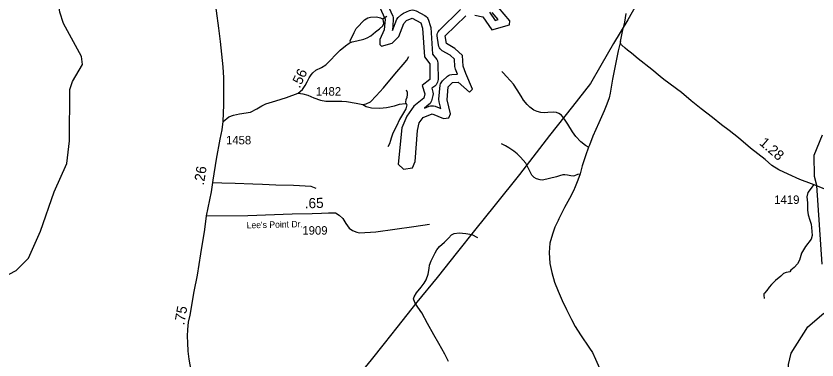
# Model space of a CAD drawing. Extents: x 2290615 to 2522933, y 819489 to 1012715.
# Drawn here: x 2339390 to 2351212, y 992330 to 997402 of the extents above; entities that cross this region are included whole.
import ezdxf

# ---------------------------------------------------------------- set-up
doc = ezdxf.new("R2010")
doc.units = 0
for name, color, linetype in [('Exist Hydrographic Buffer Line', 7, 'Continuous'), ('Exist Hydrographic Creek Single Shore', 7, 'Continuous'), ('Exist Hydrographic Lake Shore', 7, 'Continuous'), ('Exist Hydrographic Misc Water Feature', 7, 'Continuous'), ('Exist Road Non-System Type 51', 7, 'Continuous'), ('Exist Road Secondary Mileage Tenths English Label', 7, 'Continuous'), ('Exist Road Secondary Type 51 Attributed', 7, 'Continuous'), ('Exist Road Secondary Type 51 Label', 7, 'Continuous'), ('Exist Road Secondary Type 51 Number Label', 7, 'Continuous'), ('Exist Utilities Electrical Transmission Line', 7, 'Continuous')]:
    doc.layers.add(name, color=color, linetype=linetype)

msp = doc.modelspace()

# ---------------------------------------------------------------- linework, layer by layer
at = {"layer": 'Exist Hydrographic Buffer Line'}
for points in [[(2344862, 997590), (2344951, 997399), (2344956, 997379), (2344958, 997347), (2344945, 997188)], [(2344945, 997188), (2345010, 997354), (2345029, 997379), (2345078, 997427), (2345107, 997445), (2345197, 997484), (2345217, 997490), (2345238, 997491), (2345259, 997490), (2345294, 997477), (2345424, 997408), (2345441, 997396), (2345456, 997382), (2345468, 997364), (2345478, 997341), (2345504, 997260), (2345510, 997232), (2345537, 996842), (2345600, 996759)], [(2345662, 996036), (2345636, 996139), (2345632, 996178), (2345649, 996380), (2345654, 996400), (2345663, 996419), (2345685, 996447), (2345756, 996513), (2345773, 996525), (2345792, 996534), (2345823, 996541), (2345905, 996547), (2345876, 996620), (2345868, 996656), (2345861, 996765), (2345797, 996824), (2345682, 996891), (2345665, 996903), (2345650, 996918), (2345638, 996935), (2345629, 996954), (2345624, 996976), (2345604, 997109), (2345606, 997130), (2345611, 997150), (2345620, 997169), (2345641, 997195), (2345952, 997496)], [(2346377, 997461), (2346464, 997338), (2346506, 997349), (2346419, 997452)], [(2345600, 996759), (2345609, 996740), (2345616, 996701), (2345619, 996466), (2345617, 996446), (2345612, 996425), (2345603, 996406), (2345591, 996389), (2345571, 996370), (2345525, 996336), (2345544, 996277), (2345546, 996257), (2345543, 996228), (2345523, 996149), (2345514, 996130), (2345502, 996113), (2345485, 996096), (2345420, 996045), (2345489, 996072), (2345509, 996077), (2345530, 996079), (2345551, 996077), (2345574, 996071), (2345662, 996036)]]:
    msp.add_lwpolyline(points, dxfattribs=at)
at = {"layer": 'Exist Hydrographic Creek Single Shore'}
for points in [[(2351289, 993744), (2351208, 994903), (2351173, 995036), (2351169, 995351), (2351291, 995651)], [(2348630, 990329), (2349206, 990254), (2349348, 990273), (2349620, 990501), (2349711, 990518), (2349812, 990492), (2349978, 990522), (2350217, 990758), (2350424, 990810), (2350713, 991045), (2350795, 991179), (2350817, 991430), (2350790, 992263), (2350830, 992432), (2351075, 992816), (2351314, 993019)]]:
    msp.add_lwpolyline(points, dxfattribs=at)
at = {"layer": 'Exist Hydrographic Lake Shore'}
for points in [[(2344753, 997539), (2344838, 997358), (2344823, 997200), (2344759, 997056), (2344759, 996981), (2344785, 996956), (2344942, 997001), (2345041, 997101), (2345114, 997294), (2345155, 997335), (2345238, 997371), (2345364, 997304), (2345390, 997223), (2345420, 996798), (2345496, 996699), (2345499, 996466), (2345383, 996379), (2345426, 996257), (2345410, 996190), (2345262, 996072), (2345156, 995927), (2345083, 995753), (2345031, 995219), (2345107, 995144), (2345240, 995162), (2345280, 995256), (2345316, 995714), (2345340, 995829), (2345397, 995907), (2345530, 995959), (2345697, 995893), (2345780, 995903), (2345805, 995960), (2345752, 996168), (2345767, 996359), (2345833, 996421), (2345916, 996428), (2346084, 996280), (2346125, 996325), (2346031, 996554), (2345988, 996664), (2345978, 996821), (2345868, 996921), (2345742, 996995), (2345724, 997109), (2346029, 997404)], [(2346162, 997416), (2346279, 997391), (2346415, 997200), (2346672, 997270), (2346680, 997329), (2346511, 997529)]]:
    msp.add_lwpolyline(points, dxfattribs=at)
at = {"layer": 'Exist Hydrographic Misc Water Feature'}
msp.add_lwpolyline([(2337829, 992723), (2338183, 993079), (2338299, 993130), (2338699, 993160), (2338839, 993228), (2339185, 993541), (2339392, 993651), (2339574, 993829), (2339752, 994230), (2339953, 994807), (2340140, 995228), (2340178, 995561), (2340185, 996320), (2340225, 996436), (2340372, 996688), (2340354, 996803), (2340090, 997291), (2340038, 997459), (2340011, 997642), (2340034, 997774), (2340172, 998102), (2340186, 998335)], dxfattribs=at)
at = {"layer": 'Exist Road Non-System Type 51'}
for points in [[(2344328, 997011), (2344322, 997042), (2344349, 997094), (2344380, 997159), (2344412, 997218), (2344451, 997259), (2344497, 997313), (2344534, 997346), (2344581, 997377), (2344621, 997386), (2344710, 997389), (2344767, 997375), (2344801, 997359), (2344861, 997401)], [(2348311, 997028), (2348277, 996888), (2348228, 996645), (2348196, 996471), (2348159, 996264), (2348143, 996196), (2348110, 996102), (2348070, 996005), (2347990, 995828), (2347904, 995629), (2347852, 995499), (2347840, 995467)], [(2348311, 997028), (2348277, 996888), (2348228, 996645), (2348196, 996471), (2348159, 996264), (2348143, 996196), (2348110, 996102), (2348070, 996005), (2347990, 995828), (2347904, 995629), (2347852, 995499), (2347840, 995467)], [(2344508, 996099), (2344556, 996105), (2344621, 996139), (2344703, 996223), (2344813, 996342), (2344908, 996454), (2345010, 996579), (2345102, 996685), (2345156, 996753), (2345190, 996803)], [(2347840, 995467), (2347794, 995492), (2347725, 995547), (2347652, 995624), (2347604, 995694), (2347534, 995805), (2347485, 995882), (2347439, 995938), (2347402, 995963), (2347366, 995977), (2347320, 995982), (2347240, 995977), (2347184, 995974), (2347134, 995978), (2347080, 995993), (2347034, 996015), (2346973, 996056), (2346935, 996097), (2346882, 996163), (2346847, 996218), (2346788, 996312), (2346733, 996395), (2346687, 996446), (2346624, 996516), (2346585, 996557), (2346559, 996585)], [(2347840, 995467), (2347794, 995492), (2347725, 995547), (2347652, 995624), (2347604, 995694), (2347534, 995805), (2347485, 995882), (2347439, 995938), (2347402, 995963), (2347366, 995977), (2347320, 995982), (2347240, 995977), (2347184, 995974), (2347134, 995978), (2347080, 995993), (2347034, 996015), (2346973, 996056), (2346935, 996097), (2346882, 996163), (2346847, 996218), (2346788, 996312), (2346733, 996395), (2346687, 996446), (2346624, 996516), (2346585, 996557), (2346559, 996585)], [(2343554, 996263), (2343625, 996255), (2343697, 996234), (2343783, 996195), (2343885, 996161), (2343964, 996148), (2344068, 996144), (2344200, 996147), (2344270, 996141), (2344412, 996116), (2344486, 996103), (2344508, 996099)], [(2345147, 996110), (2345141, 996130), (2345149, 996169), (2345163, 996206), (2345169, 996239), (2345169, 996276), (2345154, 996310)], [(2344508, 996099), (2344558, 996066), (2344637, 996048), (2344759, 996043), (2344860, 996051), (2344976, 996078), (2345051, 996102), (2345135, 996114), (2345147, 996110), (2345157, 996093), (2345143, 996031), (2345107, 995974), (2345051, 995876), (2345006, 995780), (2344952, 995676), (2344927, 995602), (2344916, 995564), (2344904, 995515), (2344876, 995471)], [(2347715, 995073), (2347711, 995071), (2347677, 995063), (2347635, 995046), (2347613, 995042), (2347579, 995043), (2347527, 995055), (2347491, 995062), (2347461, 995062), (2347413, 995047), (2347366, 995029), (2347160, 994983), (2347126, 994984), (2347072, 995001), (2347036, 995023), (2347003, 995053), (2346967, 995126), (2346913, 995233), (2346836, 995322), (2346786, 995370), (2346737, 995407), (2346663, 995458), (2346616, 995486), (2346554, 995519)], [(2347840, 995467), (2347794, 995342), (2347746, 995193), (2347721, 995095), (2347715, 995073)], [(2347840, 995467), (2347794, 995342), (2347746, 995193), (2347721, 995095), (2347715, 995073)], [(2347715, 995073), (2347684, 994983), (2347643, 994882), (2347616, 994824), (2347557, 994709), (2347485, 994576), (2347403, 994409), (2347392, 994387), (2347343, 994287), (2347306, 994186), (2347271, 994050), (2347261, 993916), (2347271, 993754), (2347297, 993618), (2347340, 993475), (2347392, 993344), (2347451, 993206), (2347513, 993073), (2347587, 992926), (2347642, 992821), (2347722, 992700), (2347856, 992505), (2347897, 992438), (2347942, 992342), (2348001, 992207)], [(2343821, 994858), (2343746, 994890), (2343486, 994901), (2343225, 994909), (2343027, 994919), (2342883, 994921), (2342625, 994933), (2342430, 994938), (2342295, 994943)], [(2343821, 994858), (2343746, 994890), (2343486, 994901), (2343225, 994909), (2343027, 994919), (2342883, 994921), (2342625, 994933), (2342430, 994938), (2342295, 994943)], [(2351160, 994914), (2351127, 994862), (2351077, 994799), (2351062, 994737), (2351074, 994647), (2351074, 994537), (2351080, 994469), (2351106, 994391), (2351127, 994332), (2351133, 994281), (2351139, 994165), (2351124, 994111), (2351044, 994004), (2350981, 993906), (2350955, 993802), (2350922, 993748), (2350875, 993693), (2350827, 993652), (2350810, 993631), (2350786, 993625), (2350756, 993622), (2350717, 993607), (2350676, 993568), (2350598, 993500), (2350542, 993443), (2350506, 993402), (2350470, 993354), (2350438, 993315), (2350426, 993303), (2350429, 993283), (2350432, 993238)], [(2345771, 992306), (2345720, 992416), (2345631, 992574), (2345559, 992702), (2345464, 992867), (2345378, 993024), (2345320, 993108), (2345274, 993178), (2345258, 993231), (2345264, 993262), (2345302, 993321), (2345369, 993402), (2345415, 993460), (2345442, 993510), (2345473, 993594), (2345488, 993680), (2345492, 993729), (2345515, 993793), (2345552, 993862), (2345574, 993909), (2345602, 993955), (2345641, 994004), (2345715, 994065), (2345773, 994124), (2345819, 994174), (2345859, 994197), (2345931, 994205), (2346030, 994197), (2346115, 994180), (2346203, 994135)]]:
    msp.add_lwpolyline(points, dxfattribs=at)
at = {"layer": 'Exist Road Secondary Type 51 Attributed'}
for points in [[(2342447, 995848), (2342456, 996092), (2342456, 996306), (2342455, 996490), (2342449, 996655), (2342410, 997028), (2342382, 997224), (2342351, 997479), (2342328, 997614), (2342319, 997674)], [(2351344, 994846), (2351130, 994925), (2350961, 994989), (2350784, 995070), (2350650, 995132), (2350544, 995199), (2350445, 995285), (2350229, 995455), (2350054, 995604), (2349914, 995714), (2349800, 995796), (2349671, 995905), (2349504, 996031), (2349357, 996149), (2349214, 996276), (2348953, 996464), (2348895, 996511), (2348772, 996613), (2348574, 996771), (2348473, 996856), (2348417, 996897), (2348381, 996929), (2348330, 996974), (2348326, 996978), (2348320, 996986), (2348314, 996996), (2348312, 997006), (2348311, 997028), (2348343, 997176), (2348374, 997312), (2348396, 997440)], [(2342447, 995848), (2342531, 995914), (2342601, 995942), (2342687, 995958), (2342853, 995986), (2342946, 996034), (2343019, 996077), (2343078, 996105), (2343224, 996150), (2343380, 996200), (2343554, 996263), (2343618, 996318), (2343658, 996377), (2343689, 996430), (2343717, 996489), (2343745, 996537), (2343771, 996566), (2343813, 996604), (2343900, 996645), (2343962, 996683), (2344005, 996725), (2344132, 996852), (2344174, 996900), (2344255, 996963), (2344305, 997001), (2344353, 997023), (2344420, 997038), (2344521, 997060), (2344573, 997082), (2344627, 997111), (2344697, 997170), (2344756, 997214), (2344806, 997257), (2344820, 997290), (2344810, 997356)], [(2342201, 994455), (2342275, 994810), (2342301, 994981), (2342351, 995292), (2342403, 995584), (2342433, 995725), (2342447, 995848)], [(2342201, 994455), (2342812, 994461), (2343466, 994483), (2343760, 994491), (2343899, 994493), (2344000, 994498), (2344059, 994502), (2344104, 994498), (2344160, 994467), (2344214, 994416), (2344260, 994342), (2344305, 994275), (2344355, 994238), (2344418, 994212), (2344457, 994206), (2344702, 994221), (2345260, 994299), (2345491, 994333)], [(2341975, 992172), (2341945, 992340), (2341931, 992459), (2341925, 992580), (2341922, 992680), (2341925, 992780), (2341938, 992886), (2341961, 992990), (2342021, 993338), (2342066, 993581), (2342120, 993893), (2342176, 994252), (2342201, 994455)]]:
    msp.add_lwpolyline(points, dxfattribs=at)
at = {"layer": 'Exist Utilities Electrical Transmission Line'}
msp.add_lwpolyline([(2349641, 999561), (2349590, 999459), (2349406, 999103), (2349111, 998571), (2348972, 998312), (2348815, 998034), (2348611, 997691), (2348422, 997347), (2348208, 996997), (2348022, 996673), (2347867, 996405), (2347605, 996066), (2347266, 995638), (2346819, 995064), (2346461, 994616), (2346159, 994237), (2345907, 993924), (2345606, 993548), (2345308, 993180), (2345011, 992809), (2344822, 992573), (2344631, 992332), (2344499, 992169)], dxfattribs=at)

# ---------------------------------------------------------------- texts
at = {"layer": 'Exist Road Secondary Mileage Tenths English Label'}
for s, rotation, p in [('.56', 64.6693, (2343575, 996328)), ('1.28', 319.0592, (2350350, 995515)), ('.26', 80.948, (2342161, 994901)), ('.65', 1.2865, (2343653, 994566)), ('.75', 80.1673, (2341872, 992837))]:
    msp.add_text(s, height=150, rotation=rotation, dxfattribs=at).set_placement(p)
at = {"layer": 'Exist Road Secondary Type 51 Label'}
msp.add_text("Lee's Point Dr.", height=95, rotation=1.2537, dxfattribs=at).set_placement((2342795, 994270))
at = {"layer": 'Exist Road Secondary Type 51 Number Label'}
for s, p in [('1482', (2343816, 996228)), ('1458', (2342489, 995509)), ('1419', (2350581, 994631)), ('1909', (2343616, 994178))]:
    msp.add_text(s, height=125, dxfattribs=at).set_placement(p)

doc.saveas('drawing.dxf')
